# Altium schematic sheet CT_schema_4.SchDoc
size 287 x 169 mm
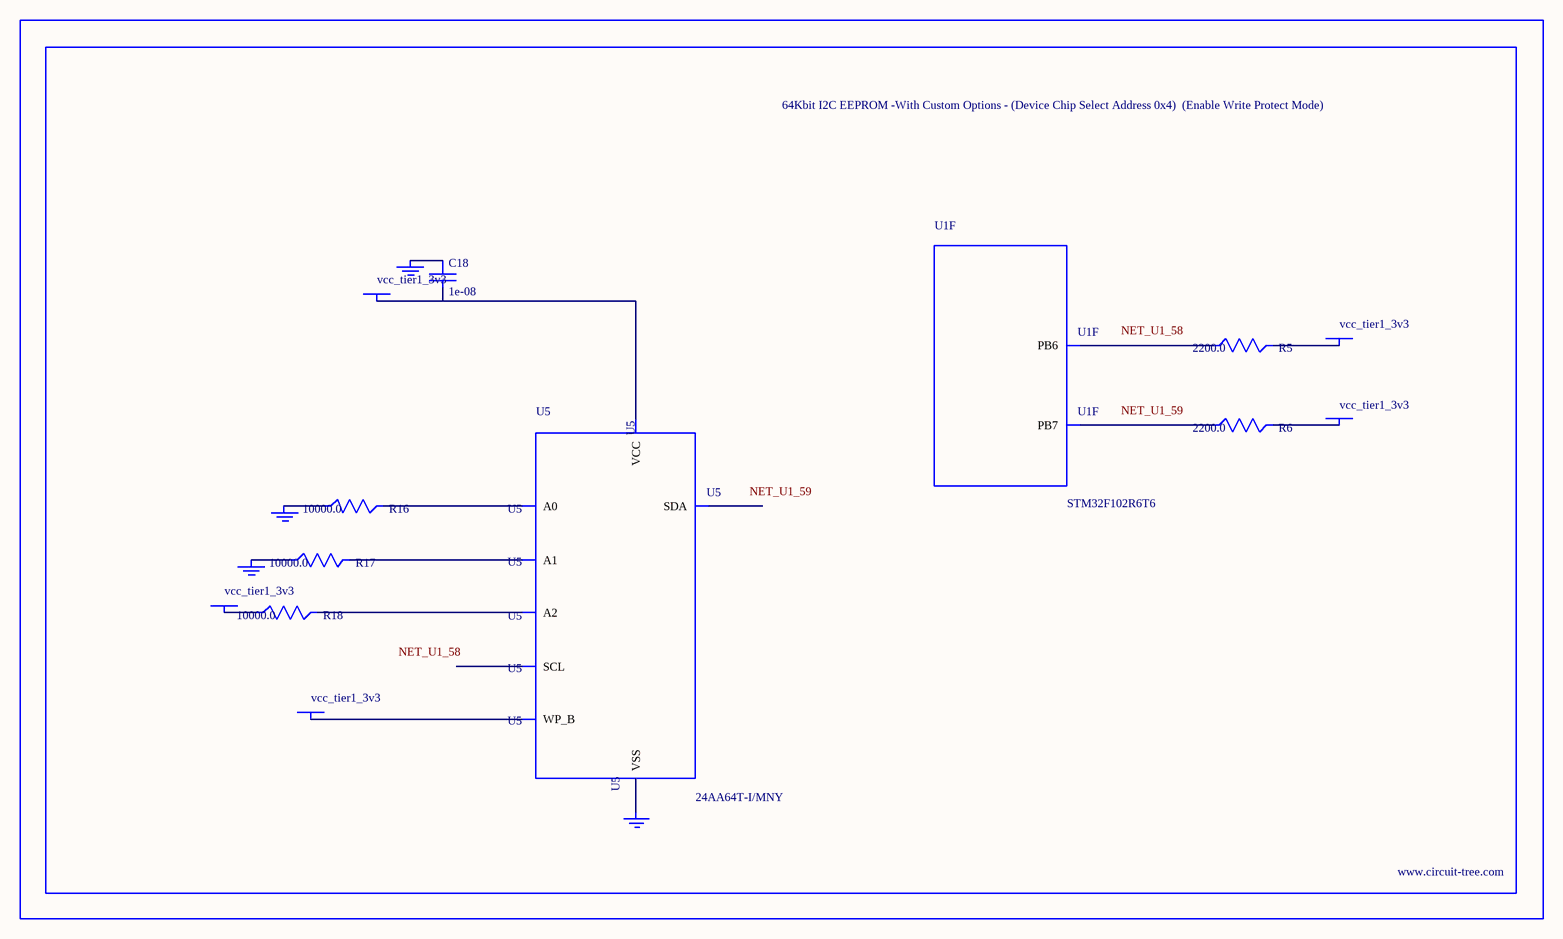
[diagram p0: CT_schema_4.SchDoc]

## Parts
BORDER3  (no value)
C18  1e-08  [C0402]
GND_INSTANCE_3_0  (no value)
GND_INSTANCE_3_1  (no value)
GND_INSTANCE_3_2  (no value)
GND_INSTANCE_3_3  (no value)
POWER_INSTANCE_3_0  vcc_tier1_3v3
POWER_INSTANCE_3_1  vcc_tier1_3v3
POWER_INSTANCE_3_2  vcc_tier1_3v3
POWER_INSTANCE_3_3  vcc_tier1_3v3
POWER_INSTANCE_3_4  vcc_tier1_3v3
R5  2200.0  [R0603]
R6  2200.0  [R0603]
R16  10000.0  [R0603]
R17  10000.0  [R0603]
R18  10000.0  [R0603]
U1  STM32F102R6T6  [LQFP64]  (part F of 7)
U5  24AA64T-I/MNY  [TDFN-8/6MM]

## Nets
NetC18_1: C18.1 GND_INSTANCE_3_2.0(GND)
NetC18_2: C18.2 POWER_INSTANCE_3_2.0(PWR) U5.8(VCC)
NetGND_INSTANCE_3_0_0: GND_INSTANCE_3_0.0(GND) R16.1
NetGND_INSTANCE_3_1_0: GND_INSTANCE_3_1.0(GND) R17.1
NetGND_INSTANCE_3_3_0: GND_INSTANCE_3_3.0(GND) U5.4(VSS)
NetPOWER_INSTANCE_3_0_0: POWER_INSTANCE_3_0.0(PWR) R18.1
NetPOWER_INSTANCE_3_1_0: POWER_INSTANCE_3_1.0(PWR) U5.7(WP_B)
NetPOWER_INSTANCE_3_3_0: POWER_INSTANCE_3_3.0(PWR) R5.2
NetPOWER_INSTANCE_3_4_0: POWER_INSTANCE_3_4.0(PWR) R6.2
NetR5_1: R5.1 U1.58(PB6)
NetR6_1: R6.1 U1.59(PB7)
NetR16_2: R16.2 U5.1(A0)
NetR17_2: R17.2 U5.2(A1)
NetR18_2: R18.2 U5.3(A2)

Not connected (* = marked no-connect by the designer): U5 5(SDA) 6(SCL)

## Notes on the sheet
- Labels drawn without touching a wire or pin: NET_U1_58, NET_U1_59

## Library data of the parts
BORDER3 = BORDER_PAGE3
C18 = C0402C103K3RAC
GND_INSTANCE_3_0-GND_INSTANCE_3_3 = GND
POWER_INSTANCE_3_0-POWER_INSTANCE_3_4 = PWR
R5 R6 = RC0603JR-072K2L
R16-R18 = RC0603JR-0710KL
